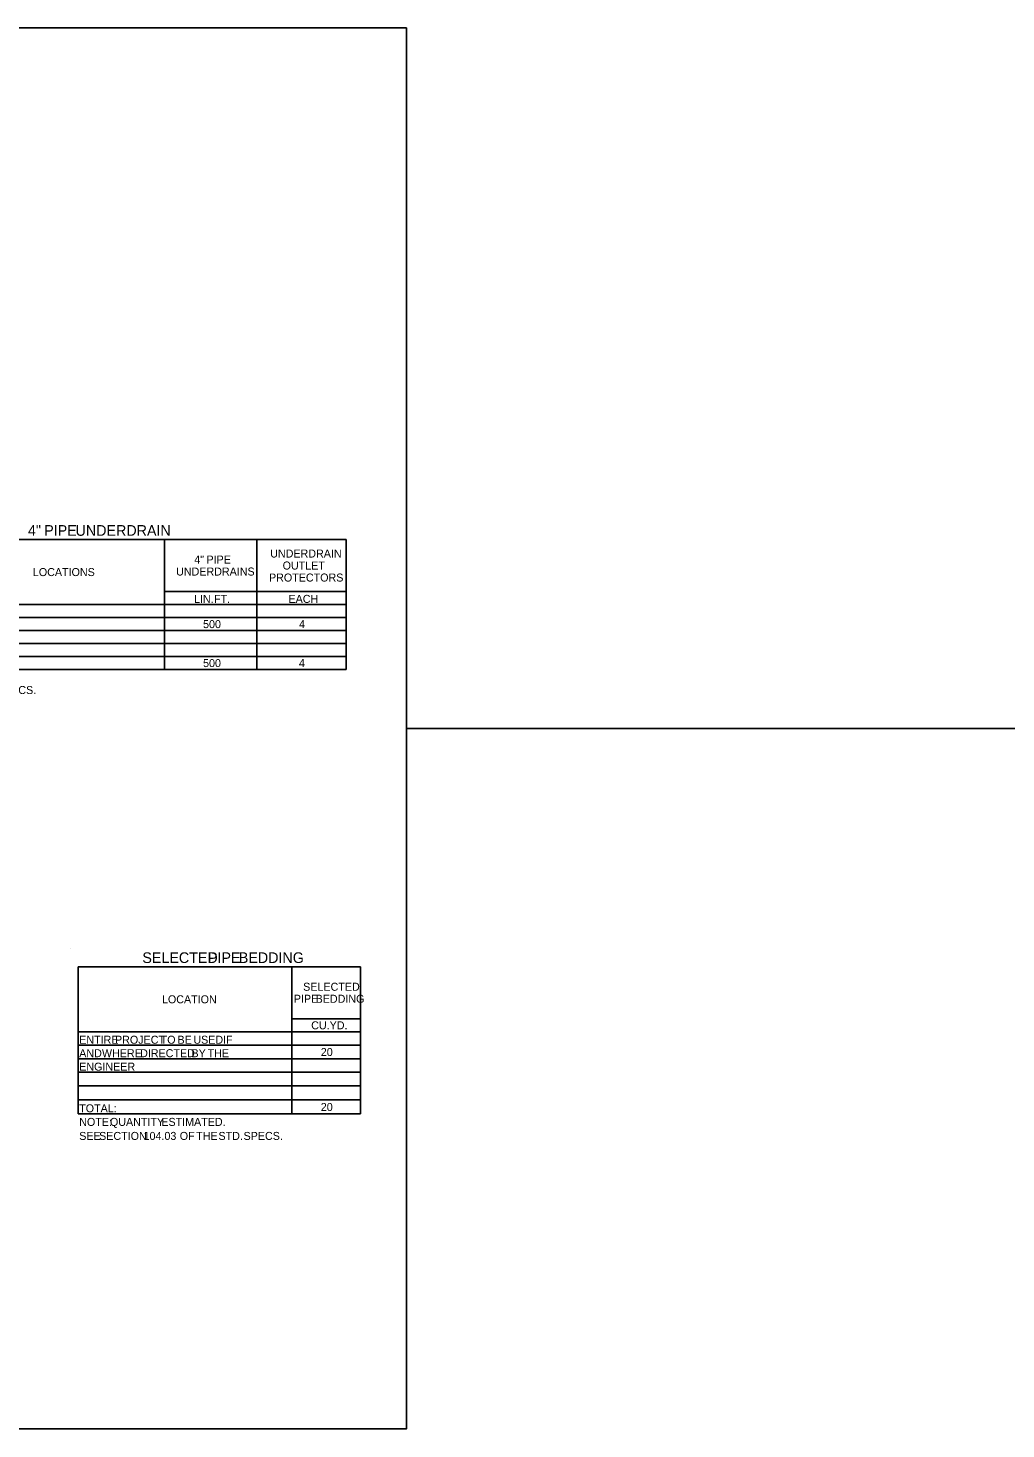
# Model space of a CAD drawing. Extents: x 3289 to 10164, y -1238 to -188.
# Drawn here: x 4630 to 5363, y -1238 to -188 of the extents above; entities that cross this region are included whole.
import ezdxf

# ---------------------------------------------------------------- set-up
doc = ezdxf.new("R2010")
doc.units = 0
for name, color, linetype in [('Default', 7, 'Continuous'), ('DSN_DRFT_Common-Annotations', 7, 'Continuous'), ('DSN_DRFT_Common-Line', 7, 'Continuous'), ('DSN_DRFT_Named-Boundary', 7, 'Continuous'), ('DSN_QNTY_Annotation', 7, 'Continuous')]:
    doc.layers.add(name, color=color, linetype=linetype)

msp = doc.modelspace()

# ---------------------------------------------------------------- linework, layer by layer
at = {"layer": 'DSN_DRFT_Common-Line'}
for p, q in [((4489.6, -571.1), (4868.4, -571.1)), ((4732.3, -668.6), (4732.3, -571.1)), ((4801.6, -668.6), (4801.6, -571.1)), ((4868.4, -668.6), (4868.4, -571.1)), ((4868.4, -668.6), (4868.4, -571.1)), ((4732.3, -610.1), (4868.4, -610.1)), ((4489.6, -619.8), (4868.4, -619.8)), ((4489.6, -629.6), (4868.4, -629.6)), ((4576.3, -619.8), (4732.3, -619.8)), ((4732.3, -629.6), (4732.3, -619.8)), ((4489.6, -639.3), (4868.4, -639.3)), ((4489.6, -649.1), (4868.4, -649.1)), ((4732.3, -668.6), (4732.3, -649.1)), ((4489.6, -658.8), (4868.4, -658.8)), ((4489.6, -668.6), (4868.4, -668.6))]:
    msp.add_line(p, q, dxfattribs=at)
at = {"layer": 'DSN_DRFT_Named-Boundary'}
for p, q in [((4913.6, -712.7), (5913.6, -712.7)), ((4661.7, -877.6), (4661.7, -877.6))]:
    msp.add_line(p, q, dxfattribs=at)
msp.add_lwpolyline([(3288.6, -1237.7), (4913.6, -1237.7), (4913.6, -187.7), (3288.6, -187.7)], close=True, dxfattribs=at)
at = {"layer": 'DSN_QNTY_Annotation'}
for p, q in [((4667.6, -891.3), (4879.3, -891.3)), ((4667.6, -1001.6), (4667.6, -891.3)), ((4667.6, -1001.6), (4667.6, -891.3)), ((4827.9, -1001.6), (4827.9, -891.3)), ((4879.3, -1001.6), (4879.3, -891.3)), ((4879.3, -1001.6), (4879.3, -891.3)), ((4827.9, -930.3), (4879.3, -930.3)), ((4667.6, -940), (4879.3, -940)), ((4827.9, -1001.6), (4827.9, -940)), ((4667.6, -950.2), (4879.3, -950.2)), ((4667.6, -960.3), (4879.3, -960.3)), ((4667.6, -970.4), (4879.3, -970.4)), ((4667.6, -980.6), (4879.3, -980.6)), ((4667.6, -991.1), (4879.3, -991.1)), ((4667.6, -1001.6), (4879.3, -1001.6))]:
    msp.add_line(p, q, dxfattribs=at)

# ---------------------------------------------------------------- texts
at = {"layer": 'Default'}
for s, height, p in [('SELECTED', 8, (4715.8, -888.5)), (' PIPE', 8, (4762, -888.5)), (' BEDDING', 8, (4785.1, -888.5)), ('LOCATION', 6, (4730.5, -918.7)), ('PIPE', 6, (4829.3, -918.3)), ('SELECTED', 6, (4836.3, -909.3)), (' BEDDING', 6, (4843.4, -918.3)), ('CU.YD.', 6, (4842.3, -938.2)), ('ENTIRE', 6, (4668.5, -949)), (' PROJECT', 6, (4693.1, -949)), (' TO', 6, (4727.3, -949)), (' BE', 6, (4739.9, -949)), (' USED', 6, (4751.8, -949)), (' IF', 6, (4774, -949)), ('AND', 6, (4668.5, -959.1)), (' WHERE', 6, (4683.3, -959.1)), (' DIRECTED', 6, (4711.9, -959.1)), (' BY', 6, (4750.4, -959.1)), (' THE', 6, (4762.5, -959.1)), ('20', 6, (4849.5, -958.2)), ('ENGINEER', 6, (4668.5, -969.2)), ('TOTAL:', 6, (4668.5, -1000.4)), ('20', 6, (4849.5, -999.4)), ('NOTE:', 6, (4668.5, -1010.6)), (' QUANTITY', 6, (4689.3, -1010.6)), (' ESTIMATED.', 6, (4727.8, -1010.6)), ('SEE', 6, (4668.5, -1021.1)), (' SECTION', 6, (4681.2, -1021.1)), (' 104.03', 6, (4714.5, -1021.1)), (' OF', 6, (4741.6, -1021.1)), (' THE', 6, (4753.9, -1021.1)), (' STD.', 6, (4770.6, -1021.1)), (' SPECS.', 6, (4789.4, -1021.1))]:
    msp.add_text(s, height=height, dxfattribs=at).set_placement(p)
at = {"layer": 'DSN_DRFT_Common-Annotations'}
for s, height, p in [('4"', 8, (4630.1, -568.3)), (' PIPE', 8, (4639.3, -568.3)), (' UNDERDRAIN', 8, (4662.8, -568.3)), ('4"', 6, (4754.7, -589.1)), (' PIPE', 6, (4761.6, -589.1)), ('UNDERDRAIN', 6, (4811.6, -584.6)), ('OUTLET', 6, (4820.9, -593.6)), ('LOCATIONS', 6, (4633.8, -598.5)), ('UNDERDRAINS', 6, (4741.1, -598.1)), ('PROTECTORS', 6, (4810.7, -602.6)), ('LIN.', 6, (4754.5, -618.6)), (' FT.', 6, (4767.3, -618.6)), ('EACH', 6, (4825.3, -618.6)), ('500', 6, (4761.3, -637.5)), ('4', 6, (4833.2, -637.5)), ('500', 6, (4761.3, -666.7)), ('4', 6, (4833.1, -666.7)), (' SPECS.', 6, (4604.6, -686.9))]:
    msp.add_text(s, height=height, dxfattribs=at).set_placement(p)

doc.saveas('drawing.dxf')
